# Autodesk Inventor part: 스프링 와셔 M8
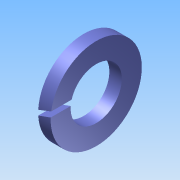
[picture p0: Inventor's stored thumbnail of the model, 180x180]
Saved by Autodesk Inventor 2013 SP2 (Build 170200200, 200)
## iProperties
Created: 2025-10
Part Number: 스프링 와셔 M8
Material: Generic
Document SubType Name: Modeling
Designer: 601
Density: 1 g/cm^3
변환 표준: STEP AP214IS
전처리기: Build: 200, Release: 2013 SP2 Update 6 - Date: Thu 07/17/2014
전송 단위: 밀리미터
불확실성: 0.01
Author: 601
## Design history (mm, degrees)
node "스프링 와셔 M81"
body "Solid1"
node "기준1"
